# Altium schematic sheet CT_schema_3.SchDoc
size 276 x 169 mm
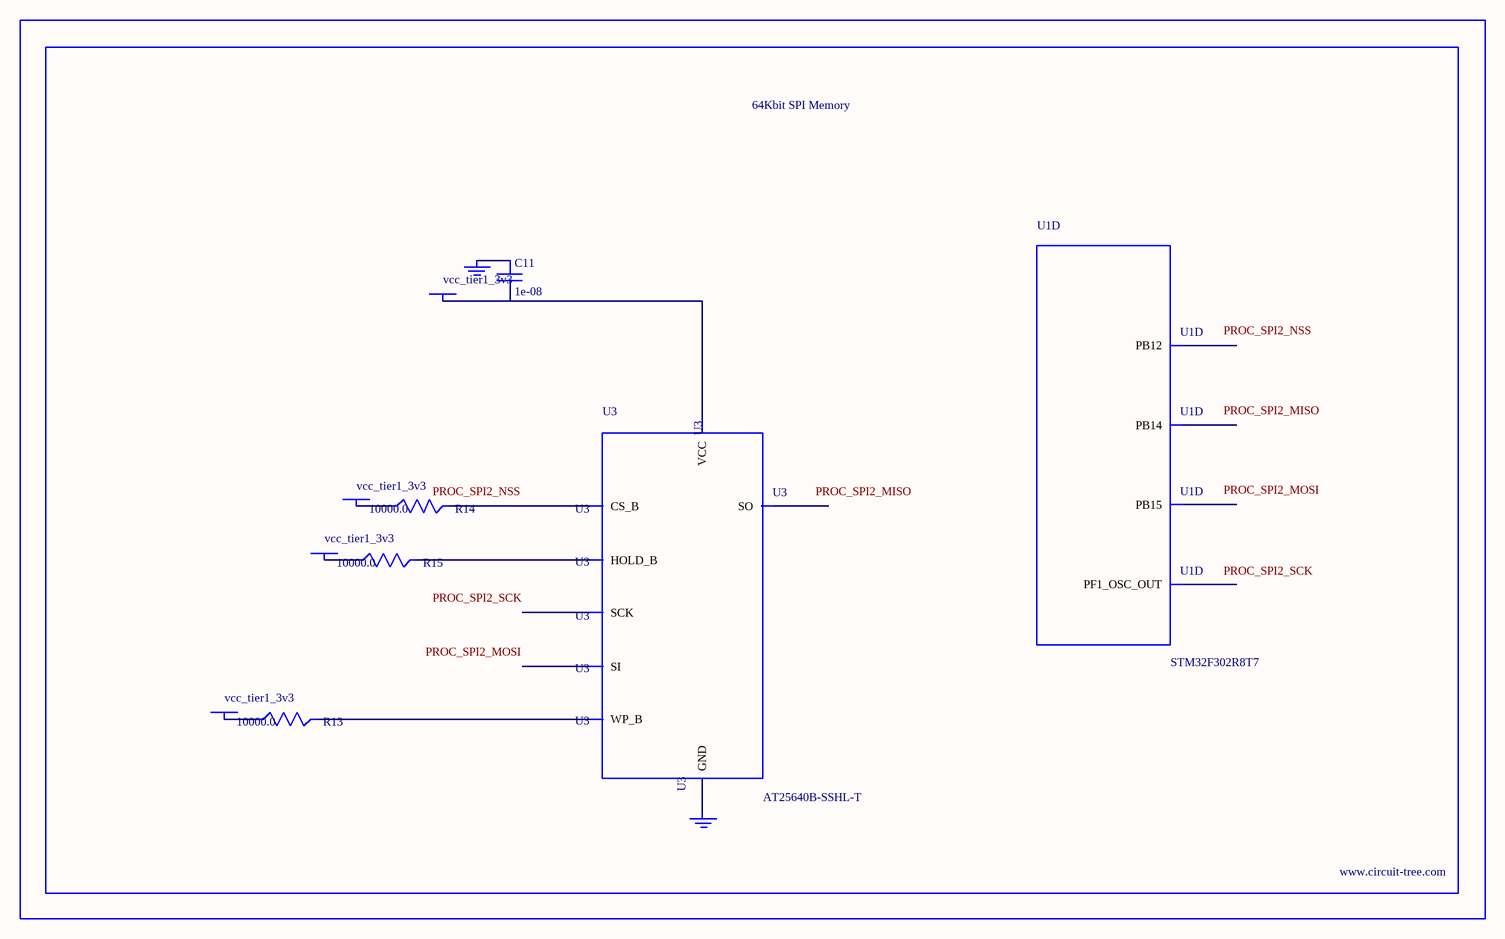
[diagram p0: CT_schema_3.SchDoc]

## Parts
BORDER2  (no value)
C11  1e-08  [C0402]
GND_INSTANCE_2_0  (no value)
GND_INSTANCE_2_1  (no value)
POWER_INSTANCE_2_0  vcc_tier1_3v3
POWER_INSTANCE_2_1  vcc_tier1_3v3
POWER_INSTANCE_2_2  vcc_tier1_3v3
POWER_INSTANCE_2_3  vcc_tier1_3v3
R13  10000.0  [R0603]
R14  10000.0  [R0603]
R15  10000.0  [R0603]
U1  STM32F302R8T7  [LQFP64]  (part D of 8)
U3  AT25640B-SSHL-T  [SOIC-8]

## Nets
NetC11_1: C11.1 GND_INSTANCE_2_0.0(GND)
NetC11_2: C11.2 POWER_INSTANCE_2_3.0(PWR) U3.8(VCC)
NetGND_INSTANCE_2_1_0: GND_INSTANCE_2_1.0(GND) U3.4(GND)
NetPOWER_INSTANCE_2_0_0: POWER_INSTANCE_2_0.0(PWR) R14.1
NetPOWER_INSTANCE_2_1_0: POWER_INSTANCE_2_1.0(PWR) R13.1
NetPOWER_INSTANCE_2_2_0: POWER_INSTANCE_2_2.0(PWR) R15.1
NetR13_2: R13.2 U3.3(WP_B)
NetR14_2: R14.2 U3.1(CS_B)
NetR15_2: R15.2 U3.7(HOLD_B)

Not connected (* = marked no-connect by the designer): U1 6(PF1_OSC_OUT) 33(PB12) 35(PB14) 36(PB15); U3 2(SO) 5(SI) 6(SCK)

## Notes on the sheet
- Labels drawn without touching a wire or pin: PROC_SPI2_MISO, PROC_SPI2_MOSI, PROC_SPI2_NSS, PROC_SPI2_SCK

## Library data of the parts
BORDER2 = BORDER_PAGE2
C11 = C0402C103K3RAC
GND_INSTANCE_2_0 GND_INSTANCE_2_1 = GND
POWER_INSTANCE_2_0-POWER_INSTANCE_2_3 = PWR
R13-R15 = RC0603JR-0710KL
